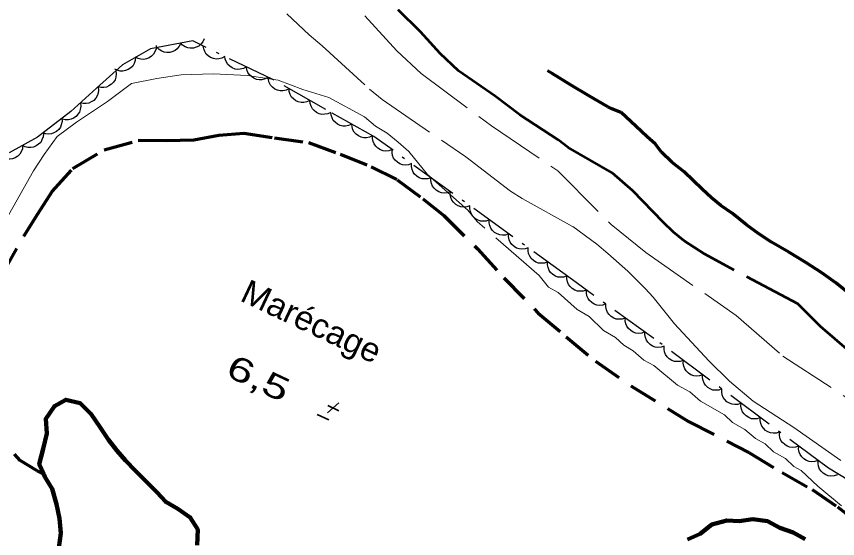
# Model space of a CAD drawing. Extents: x 355726 to 357533, y 5103782 to 5105258.
# Drawn here: x 356018.2 to 356069.6, y 5104677.9 to 5104710.5 of the extents above; entities that cross this region are included whole.
import ezdxf
from ezdxf.enums import TextEntityAlignment as Align

# ---------------------------------------------------------------- set-up
doc = ezdxf.new("R2010")
doc.units = 0
doc.header["$LTSCALE"] = 0.6
for name, pattern in [('DASH_DOUBLE_DOT', [9.2, 5, -1.2, 0.3, -1.2, 0.3, -1.2]), ('DOT_DASHED', [7.7, 5, -1.2, 0.3, -1.2]), ('LONG_DASHED', [7.5, 6, -1.5]), ('MEDIUM_DASHED', [4.5, 3, -1.5])]:
    doc.linetypes.add(name, pattern=pattern)
for name, color, linetype, lineweight in [('1', 7, 'LONG_DASHED', 53), ('2', 7, 'LONG_DASHED', 13), ('22', 7, 'Continuous', 13), ('3', 7, 'Continuous', 140), ('4', 7, 'DASH_DOUBLE_DOT', 53), ('44', 7, 'Continuous', 25), ('7', 7, 'MEDIUM_DASHED', 70)]:
    doc.layers.add(name, color=color, linetype=linetype, lineweight=lineweight)

msp = doc.modelspace()

# ---------------------------------------------------------------- linework, layer by layer
at = {"layer": '1'}
msp.add_lwpolyline([(356070.3, 5104689.58), (356068.52, 5104691.13), (356067.09, 5104692.54), (356061.28, 5104695.65), (356059.98, 5104696.49), (356059.32, 5104697.03), (356058.68, 5104697.65), (356056.77, 5104699.62), (356055.48, 5104700.74), (356052.73, 5104702.34), (356052.11, 5104702.8), (356049.7, 5104704.37), (356048.15, 5104705.54), (356045.86, 5104707.13), (356044.71, 5104708.21), (356043.49, 5104709.57), (356042.09, 5104710.94)], dxfattribs=at)
at = {"layer": '2'}
for points in [[(356035.12, 5104710.7), (356036.52, 5104709.38), (356037.34, 5104708.69), (356040.3, 5104705.98), (356041.08, 5104705.33), (356046.32, 5104701.74), (356049.12, 5104699.59), (356049.85, 5104699.13), (356053.02, 5104697.38), (356054.51, 5104696.28), (356055.2, 5104695.69), (356056.45, 5104694.59), (356057.55, 5104693.51), (356058.04, 5104692.97), (356059.38, 5104691.29), (356061.52, 5104688.98), (356062.82, 5104687.7), (356064.31, 5104686.45), (356066.84, 5104684.8), (356073.24, 5104680.34)], [(356040, 5104710.57), (356042, 5104708.38), (356043.53, 5104706.97), (356047.92, 5104703.68), (356052.07, 5104700.88), (356055.42, 5104697.51), (356057.58, 5104695.76), (356063.24, 5104691.82), (356066.16, 5104689.28), (356076.24, 5104682.7)], [(356069.83, 5104679.9), (356068.34, 5104681.13), (356067.3, 5104682.11), (356066.85, 5104682.37), (356066.33, 5104682.86), (356065.57, 5104683.29), (356065.05, 5104683.78), (356064.45, 5104684.12), (356063.78, 5104684.69), (356063.02, 5104685.12), (356062.51, 5104685.61), (356061, 5104686.46), (356060.33, 5104687.03), (356059.57, 5104687.46), (356058.08, 5104688.69), (356057.47, 5104689.03), (356056.8, 5104689.61), (356056.2, 5104689.95), (356055.68, 5104690.44), (356054.93, 5104690.87), (356054.04, 5104691.76), (356053.28, 5104692.19), (356052.1, 5104693.25), (356051.49, 5104693.59), (356050.91, 5104694.32), (356047.04, 5104697.69), (356046.45, 5104698.41), (356043.92, 5104700.63), (356042.75, 5104702.08), (356042.08, 5104702.66), (356041.41, 5104703.23), (356040.66, 5104703.66), (356039.99, 5104704.24), (356037.74, 5104705.45)]]:
    msp.add_lwpolyline(points, dxfattribs=at)
at = {"layer": '2', "linetype": 'Continuous'}
msp.add_lwpolyline([(356016.67, 5104696.28), (356019.26, 5104700.87), (356019.93, 5104701.89), (356020.76, 5104703.01), (356021.96, 5104703.91), (356023.89, 5104705.21), (356025.41, 5104706.34), (356026.98, 5104706.65), (356028.5, 5104706.88), (356030.52, 5104706.93), (356032.65, 5104706.83), (356034.57, 5104706.54), (356036.13, 5104705.96), (356037.74, 5104705.45)], dxfattribs=at)
at = {"layer": '22', "linetype": 'LONG_DASHED', "lineweight": 70}
for points in [[(356059.98, 5104700.8), (356059.22, 5104701.42), (356058.57, 5104702.04), (356058.16, 5104702.55), (356057.67, 5104702.99), (356056.97, 5104703.66), (356056.04, 5104704.53), (356055.46, 5104704.74), (356055.21, 5104704.88), (356054.06, 5104705.55), (356052.88, 5104706.26), (356051.72, 5104706.96), (356051.44, 5104707.13)], [(356070.46, 5104693.07), (356069.48, 5104693.86), (356068.59, 5104694.49), (356067.59, 5104695.13), (356066.53, 5104695.79), (356065.44, 5104696.41), (356064.65, 5104696.93), (356063.89, 5104697.49), (356063, 5104698.2), (356062.29, 5104698.7), (356061.69, 5104699.19), (356061.12, 5104699.73), (356059.98, 5104700.8)]]:
    msp.add_lwpolyline(points, dxfattribs=at)
at = {"layer": '3', "lineweight": 35}
for p, q in [((356038.38, 5104686.36), (356037.67, 5104685.72)), ((356037.68, 5104686.19), (356038.38, 5104685.86)), ((356037.02, 5104685.62), (356037.74, 5104685.28))]:
    msp.add_line(p, q, dxfattribs=at)
at = {"layer": '4', "linetype": 'Continuous', "lineweight": 90}
for points in [[(356029.51, 5104677.45), (356029.55, 5104678.42), (356029.08, 5104679.18), (356028.3, 5104679.72), (356027.54, 5104680.15), (356026.99, 5104680.76), (356026.29, 5104681.45), (356025.66, 5104682.1), (356025.03, 5104682.75), (356024.48, 5104683.36), (356023.97, 5104684.04), (356023.42, 5104684.85), (356022.88, 5104685.65), (356022.18, 5104686.34), (356021.29, 5104686.54), (356020.58, 5104686.15), (356020.04, 5104685.36), (356020.11, 5104684.43), (356019.87, 5104683.47), (356019.63, 5104682.52), (356019.91, 5104681.88), (356019.98, 5104681.73), (356020.44, 5104680.97), (356020.71, 5104680.02), (356020.9, 5104679.12), (356020.97, 5104678.19), (356020.85, 5104677.27)], [(356067.56, 5104677.82), (356066.81, 5104678.24), (356065.97, 5104678.52), (356065.21, 5104678.94), (356064.28, 5104679.07), (356063.43, 5104678.95), (356062.65, 5104678.99), (356061.71, 5104678.73), (356060.98, 5104678.15), (356060.19, 5104677.8)]]:
    msp.add_lwpolyline(points, dxfattribs=at)
at = {"layer": '44', "linetype": 'DOT_DASHED'}
msp.add_lwpolyline([(356078.19, 5104676.69), (356069.01, 5104682.26), (356058.09, 5104690.38), (356053, 5104694.04), (356040.57, 5104703.02), (356037.56, 5104704.71), (356034.24, 5104706.58), (356029.24, 5104709), (356026.59, 5104708.51), (356024.83, 5104707.51), (356023.22, 5104706.05), (356021.6, 5104704.58), (356019.51, 5104702.98), (356017.75, 5104701.99)], dxfattribs=at)
at = {"layer": '44'}
for points in [[(356026.95, 5104708.72), (356026.94, 5104708.51), (356026.86, 5104708.32), (356026.78, 5104708.18), (356026.66, 5104708.05), (356026.51, 5104707.95), (356026.33, 5104707.88), (356026.17, 5104707.84), (356025.99, 5104707.85), (356025.81, 5104707.9), (356025.65, 5104707.98)], [(356028.48, 5104708.86), (356028.39, 5104708.67), (356028.26, 5104708.51), (356028.14, 5104708.4), (356027.98, 5104708.33), (356027.8, 5104708.28), (356027.61, 5104708.28), (356027.45, 5104708.29), (356027.29, 5104708.36), (356027.13, 5104708.46), (356027, 5104708.59)], [(356029.95, 5104709.13), (356029.87, 5104708.94), (356029.74, 5104708.79), (356029.61, 5104708.68), (356029.45, 5104708.6), (356029.28, 5104708.55), (356029.08, 5104708.55), (356028.92, 5104708.56), (356028.76, 5104708.63), (356028.6, 5104708.73), (356028.48, 5104708.86)], [(356031.24, 5104708.03), (356031.06, 5104707.93), (356030.86, 5104707.88), (356030.7, 5104707.86), (356030.53, 5104707.9), (356030.35, 5104707.96), (356030.2, 5104708.07), (356030.08, 5104708.18), (356029.99, 5104708.33), (356029.92, 5104708.51), (356029.89, 5104708.68)], [(356025.65, 5104707.98), (356025.63, 5104707.77), (356025.56, 5104707.58), (356025.48, 5104707.43), (356025.35, 5104707.31), (356025.2, 5104707.21), (356025.02, 5104707.14), (356024.86, 5104707.1), (356024.69, 5104707.11), (356024.51, 5104707.16), (356024.35, 5104707.24)], [(356032.59, 5104707.38), (356032.41, 5104707.27), (356032.21, 5104707.23), (356032.05, 5104707.21), (356031.88, 5104707.24), (356031.7, 5104707.31), (356031.55, 5104707.42), (356031.43, 5104707.53), (356031.34, 5104707.68), (356031.27, 5104707.85), (356031.24, 5104708.03)], [(356033.94, 5104706.72), (356033.76, 5104706.62), (356033.56, 5104706.57), (356033.4, 5104706.56), (356033.23, 5104706.59), (356033.05, 5104706.66), (356032.9, 5104706.77), (356032.78, 5104706.88), (356032.69, 5104707.03), (356032.62, 5104707.2), (356032.59, 5104707.38)], [(356024.42, 5104707.14), (356024.45, 5104706.93), (356024.42, 5104706.73), (356024.37, 5104706.57), (356024.27, 5104706.42), (356024.15, 5104706.29), (356023.99, 5104706.18), (356023.84, 5104706.11), (356023.67, 5104706.08), (356023.48, 5104706.09), (356023.31, 5104706.13)], [(356035.26, 5104706.01), (356035.07, 5104705.91), (356034.87, 5104705.88), (356034.71, 5104705.87), (356034.54, 5104705.92), (356034.37, 5104705.99), (356034.22, 5104706.11), (356034.1, 5104706.23), (356034.02, 5104706.39), (356033.97, 5104706.56), (356033.95, 5104706.74)], [(356023.31, 5104706.13), (356023.34, 5104705.92), (356023.31, 5104705.72), (356023.26, 5104705.56), (356023.16, 5104705.41), (356023.04, 5104705.28), (356022.88, 5104705.18), (356022.73, 5104705.1), (356022.56, 5104705.08), (356022.37, 5104705.08), (356022.2, 5104705.12)], [(356036.57, 5104705.27), (356036.38, 5104705.18), (356036.18, 5104705.14), (356036.01, 5104705.14), (356035.84, 5104705.18), (356035.68, 5104705.26), (356035.53, 5104705.38), (356035.41, 5104705.49), (356035.33, 5104705.65), (356035.27, 5104705.83), (356035.26, 5104706.01)], [(356022.2, 5104705.12), (356022.23, 5104704.91), (356022.19, 5104704.71), (356022.15, 5104704.55), (356022.05, 5104704.41), (356021.93, 5104704.27), (356021.77, 5104704.17), (356021.62, 5104704.1), (356021.45, 5104704.07), (356021.26, 5104704.07), (356021.08, 5104704.11)], [(356037.87, 5104704.53), (356037.69, 5104704.44), (356037.49, 5104704.41), (356037.32, 5104704.4), (356037.15, 5104704.44), (356036.98, 5104704.52), (356036.83, 5104704.64), (356036.72, 5104704.76), (356036.64, 5104704.91), (356036.58, 5104705.09), (356036.57, 5104705.27)], [(356021.05, 5104704.16), (356021.06, 5104703.95), (356021.01, 5104703.75), (356020.95, 5104703.6), (356020.85, 5104703.46), (356020.71, 5104703.33), (356020.54, 5104703.24), (356020.39, 5104703.18), (356020.21, 5104703.17), (356020.03, 5104703.19), (356019.86, 5104703.25)], [(356039.18, 5104703.8), (356038.99, 5104703.71), (356038.79, 5104703.67), (356038.63, 5104703.67), (356038.46, 5104703.71), (356038.29, 5104703.79), (356038.14, 5104703.91), (356038.03, 5104704.02), (356037.95, 5104704.18), (356037.89, 5104704.35), (356037.87, 5104704.53)], [(356040.49, 5104703.07), (356040.3, 5104702.97), (356040.1, 5104702.94), (356039.94, 5104702.93), (356039.77, 5104702.98), (356039.6, 5104703.05), (356039.45, 5104703.17), (356039.33, 5104703.29), (356039.25, 5104703.44), (356039.2, 5104703.62), (356039.18, 5104703.8)], [(356019.89, 5104703.19), (356019.87, 5104702.99), (356019.8, 5104702.8), (356019.72, 5104702.65), (356019.59, 5104702.53), (356019.44, 5104702.43), (356019.26, 5104702.36), (356019.1, 5104702.32), (356018.92, 5104702.34), (356018.74, 5104702.38), (356018.58, 5104702.46)], [(356041.71, 5104702.2), (356041.51, 5104702.12), (356041.31, 5104702.11), (356041.15, 5104702.13), (356040.98, 5104702.19), (356040.82, 5104702.28), (356040.69, 5104702.42), (356040.59, 5104702.55), (356040.53, 5104702.71), (356040.49, 5104702.89), (356040.49, 5104703.07)], [(356018.58, 5104702.46), (356018.57, 5104702.25), (356018.49, 5104702.06), (356018.41, 5104701.92), (356018.28, 5104701.79), (356018.13, 5104701.69), (356017.95, 5104701.63), (356017.79, 5104701.59), (356017.62, 5104701.6), (356017.44, 5104701.64), (356017.28, 5104701.72)], [(356042.93, 5104701.32), (356042.73, 5104701.25), (356042.53, 5104701.23), (356042.36, 5104701.25), (356042.2, 5104701.31), (356042.04, 5104701.41), (356041.91, 5104701.54), (356041.8, 5104701.67), (356041.74, 5104701.83), (356041.71, 5104702.02), (356041.71, 5104702.2)], [(356044.14, 5104700.44), (356043.95, 5104700.37), (356043.74, 5104700.36), (356043.58, 5104700.37), (356043.41, 5104700.43), (356043.26, 5104700.53), (356043.12, 5104700.66), (356043.02, 5104700.79), (356042.96, 5104700.96), (356042.92, 5104701.14), (356042.93, 5104701.32)], [(356045.36, 5104699.56), (356045.16, 5104699.49), (356044.96, 5104699.48), (356044.79, 5104699.49), (356044.63, 5104699.55), (356044.47, 5104699.65), (356044.34, 5104699.79), (356044.24, 5104699.91), (356044.17, 5104700.08), (356044.14, 5104700.26), (356044.14, 5104700.44)], [(356046.57, 5104698.68), (356046.38, 5104698.61), (356046.17, 5104698.6), (356046.01, 5104698.61), (356045.85, 5104698.68), (356045.69, 5104698.77), (356045.55, 5104698.91), (356045.45, 5104699.03), (356045.39, 5104699.2), (356045.35, 5104699.38), (356045.36, 5104699.56)], [(356047.79, 5104697.8), (356047.59, 5104697.73), (356047.39, 5104697.72), (356047.23, 5104697.73), (356047.06, 5104697.8), (356046.9, 5104697.89), (356046.77, 5104698.03), (356046.67, 5104698.16), (356046.61, 5104698.32), (356046.57, 5104698.5), (356046.57, 5104698.68)], [(356049.01, 5104696.93), (356048.81, 5104696.85), (356048.61, 5104696.84), (356048.44, 5104696.86), (356048.28, 5104696.92), (356048.12, 5104697.01), (356047.98, 5104697.15), (356047.88, 5104697.28), (356047.82, 5104697.44), (356047.78, 5104697.62), (356047.79, 5104697.8)], [(356050.22, 5104696.05), (356050.03, 5104695.98), (356049.82, 5104695.96), (356049.66, 5104695.98), (356049.49, 5104696.04), (356049.34, 5104696.13), (356049.2, 5104696.27), (356049.1, 5104696.4), (356049.04, 5104696.56), (356049, 5104696.75), (356049.01, 5104696.93)], [(356051.44, 5104695.17), (356051.24, 5104695.1), (356051.04, 5104695.09), (356050.87, 5104695.1), (356050.71, 5104695.16), (356050.55, 5104695.26), (356050.42, 5104695.39), (356050.32, 5104695.52), (356050.25, 5104695.69), (356050.22, 5104695.87), (356050.22, 5104696.05)], [(356052.65, 5104694.29), (356052.46, 5104694.22), (356052.25, 5104694.21), (356052.09, 5104694.22), (356051.93, 5104694.28), (356051.77, 5104694.38), (356051.63, 5104694.51), (356051.53, 5104694.64), (356051.47, 5104694.81), (356051.43, 5104694.99), (356051.44, 5104695.17)], [(356053.87, 5104693.41), (356053.67, 5104693.34), (356053.47, 5104693.33), (356053.31, 5104693.34), (356053.14, 5104693.41), (356052.98, 5104693.5), (356052.85, 5104693.64), (356052.75, 5104693.76), (356052.68, 5104693.93), (356052.65, 5104694.11), (356052.65, 5104694.29)], [(356055.09, 5104692.54), (356054.89, 5104692.47), (356054.69, 5104692.45), (356054.53, 5104692.47), (356054.36, 5104692.53), (356054.2, 5104692.62), (356054.07, 5104692.76), (356053.97, 5104692.89), (356053.9, 5104693.05), (356053.87, 5104693.23), (356053.87, 5104693.41)], [(356056.31, 5104691.66), (356056.11, 5104691.59), (356055.91, 5104691.58), (356055.74, 5104691.59), (356055.58, 5104691.65), (356055.42, 5104691.75), (356055.29, 5104691.88), (356055.18, 5104692.01), (356055.12, 5104692.18), (356055.08, 5104692.36), (356055.09, 5104692.54)], [(356057.52, 5104690.79), (356057.33, 5104690.71), (356057.13, 5104690.7), (356056.96, 5104690.72), (356056.8, 5104690.78), (356056.64, 5104690.87), (356056.5, 5104691.01), (356056.4, 5104691.14), (356056.34, 5104691.3), (356056.3, 5104691.48), (356056.31, 5104691.66)], [(356058.73, 5104689.9), (356058.54, 5104689.83), (356058.33, 5104689.82), (356058.17, 5104689.84), (356058.01, 5104689.9), (356057.85, 5104690), (356057.72, 5104690.14), (356057.62, 5104690.27), (356057.56, 5104690.43), (356057.52, 5104690.62), (356057.53, 5104690.8)], [(356059.94, 5104689.01), (356059.74, 5104688.94), (356059.54, 5104688.93), (356059.37, 5104688.94), (356059.21, 5104689.01), (356059.05, 5104689.11), (356058.92, 5104689.24), (356058.82, 5104689.37), (356058.76, 5104689.54), (356058.73, 5104689.72), (356058.73, 5104689.9)], [(356061.14, 5104688.11), (356060.94, 5104688.04), (356060.74, 5104688.03), (356060.58, 5104688.05), (356060.41, 5104688.11), (356060.26, 5104688.21), (356060.12, 5104688.35), (356060.02, 5104688.48), (356059.96, 5104688.64), (356059.93, 5104688.83), (356059.94, 5104689.01)], [(356062.35, 5104687.22), (356062.15, 5104687.15), (356061.95, 5104687.14), (356061.78, 5104687.15), (356061.62, 5104687.22), (356061.46, 5104687.32), (356061.33, 5104687.45), (356061.23, 5104687.58), (356061.17, 5104687.75), (356061.13, 5104687.93), (356061.14, 5104688.11)], [(356063.55, 5104686.32), (356063.35, 5104686.25), (356063.15, 5104686.24), (356062.98, 5104686.26), (356062.82, 5104686.32), (356062.66, 5104686.42), (356062.53, 5104686.56), (356062.43, 5104686.69), (356062.37, 5104686.85), (356062.34, 5104687.04), (356062.35, 5104687.22)], [(356064.75, 5104685.43), (356064.56, 5104685.36), (356064.35, 5104685.35), (356064.19, 5104685.36), (356064.03, 5104685.43), (356063.87, 5104685.53), (356063.74, 5104685.66), (356063.64, 5104685.79), (356063.58, 5104685.96), (356063.54, 5104686.14), (356063.55, 5104686.32)], [(356065.96, 5104684.53), (356065.76, 5104684.46), (356065.56, 5104684.45), (356065.39, 5104684.47), (356065.23, 5104684.53), (356065.07, 5104684.63), (356064.94, 5104684.77), (356064.84, 5104684.9), (356064.78, 5104685.06), (356064.75, 5104685.25), (356064.75, 5104685.43)], [(356067.16, 5104683.64), (356066.96, 5104683.57), (356066.76, 5104683.56), (356066.6, 5104683.57), (356066.43, 5104683.64), (356066.28, 5104683.74), (356066.14, 5104683.87), (356066.04, 5104684), (356065.98, 5104684.17), (356065.95, 5104684.35), (356065.96, 5104684.53)], [(356068.36, 5104682.74), (356068.17, 5104682.67), (356067.96, 5104682.66), (356067.8, 5104682.68), (356067.64, 5104682.74), (356067.48, 5104682.84), (356067.35, 5104682.98), (356067.25, 5104683.11), (356067.19, 5104683.27), (356067.15, 5104683.46), (356067.16, 5104683.64)], [(356069.57, 5104681.85), (356069.37, 5104681.78), (356069.17, 5104681.77), (356069, 5104681.78), (356068.84, 5104681.85), (356068.68, 5104681.95), (356068.55, 5104682.08), (356068.45, 5104682.21), (356068.39, 5104682.38), (356068.36, 5104682.56), (356068.36, 5104682.74)]]:
    msp.add_lwpolyline(points, dxfattribs=at)
at = {"layer": '7'}
for points in [[(356017.35, 5104694.45), (356018.67, 5104696.79), (356019.55, 5104698.18), (356020.43, 5104699.57), (356021.74, 5104701.01), (356023.7, 5104702.19), (356025.82, 5104702.78), (356027.6, 5104702.77), (356029.31, 5104702.8), (356030.87, 5104703.11), (356032.43, 5104703.23), (356034.35, 5104702.94), (356036.47, 5104702.64), (356038.45, 5104701.92), (356040.39, 5104701.13), (356042.02, 5104700.31), (356043.63, 5104699.11), (356044.94, 5104698.07), (356047.05, 5104695.99), (356048.71, 5104694.17), (356050.85, 5104691.97), (356052.6, 5104690.49), (356054.43, 5104688.96), (356056.64, 5104687.42), (356060.25, 5104685.18), (356064.04, 5104683.25), (356066.11, 5104681.99), (356068, 5104680.92), (356069.58, 5104679.84), (356071.45, 5104678.39)], [(356019.91, 5104681.88), (356019.49, 5104682.1), (356018.44, 5104682.74), (356018.07, 5104683.14)]]:
    msp.add_lwpolyline(points, dxfattribs=at)

# ---------------------------------------------------------------- texts
at = {"layer": '3', "width": 1.45}
msp.add_text('    6,5', height=1.5, rotation=334.72, dxfattribs=at).set_placement((356031.57, 5104687.906), align=Align.CENTER)
at = {"layer": '7', "width": 1.05}
msp.add_text('Marécage', height=1.5, rotation=334.72, dxfattribs=at).set_placement((356032.12, 5104692.77))

doc.saveas('drawing.dxf')
